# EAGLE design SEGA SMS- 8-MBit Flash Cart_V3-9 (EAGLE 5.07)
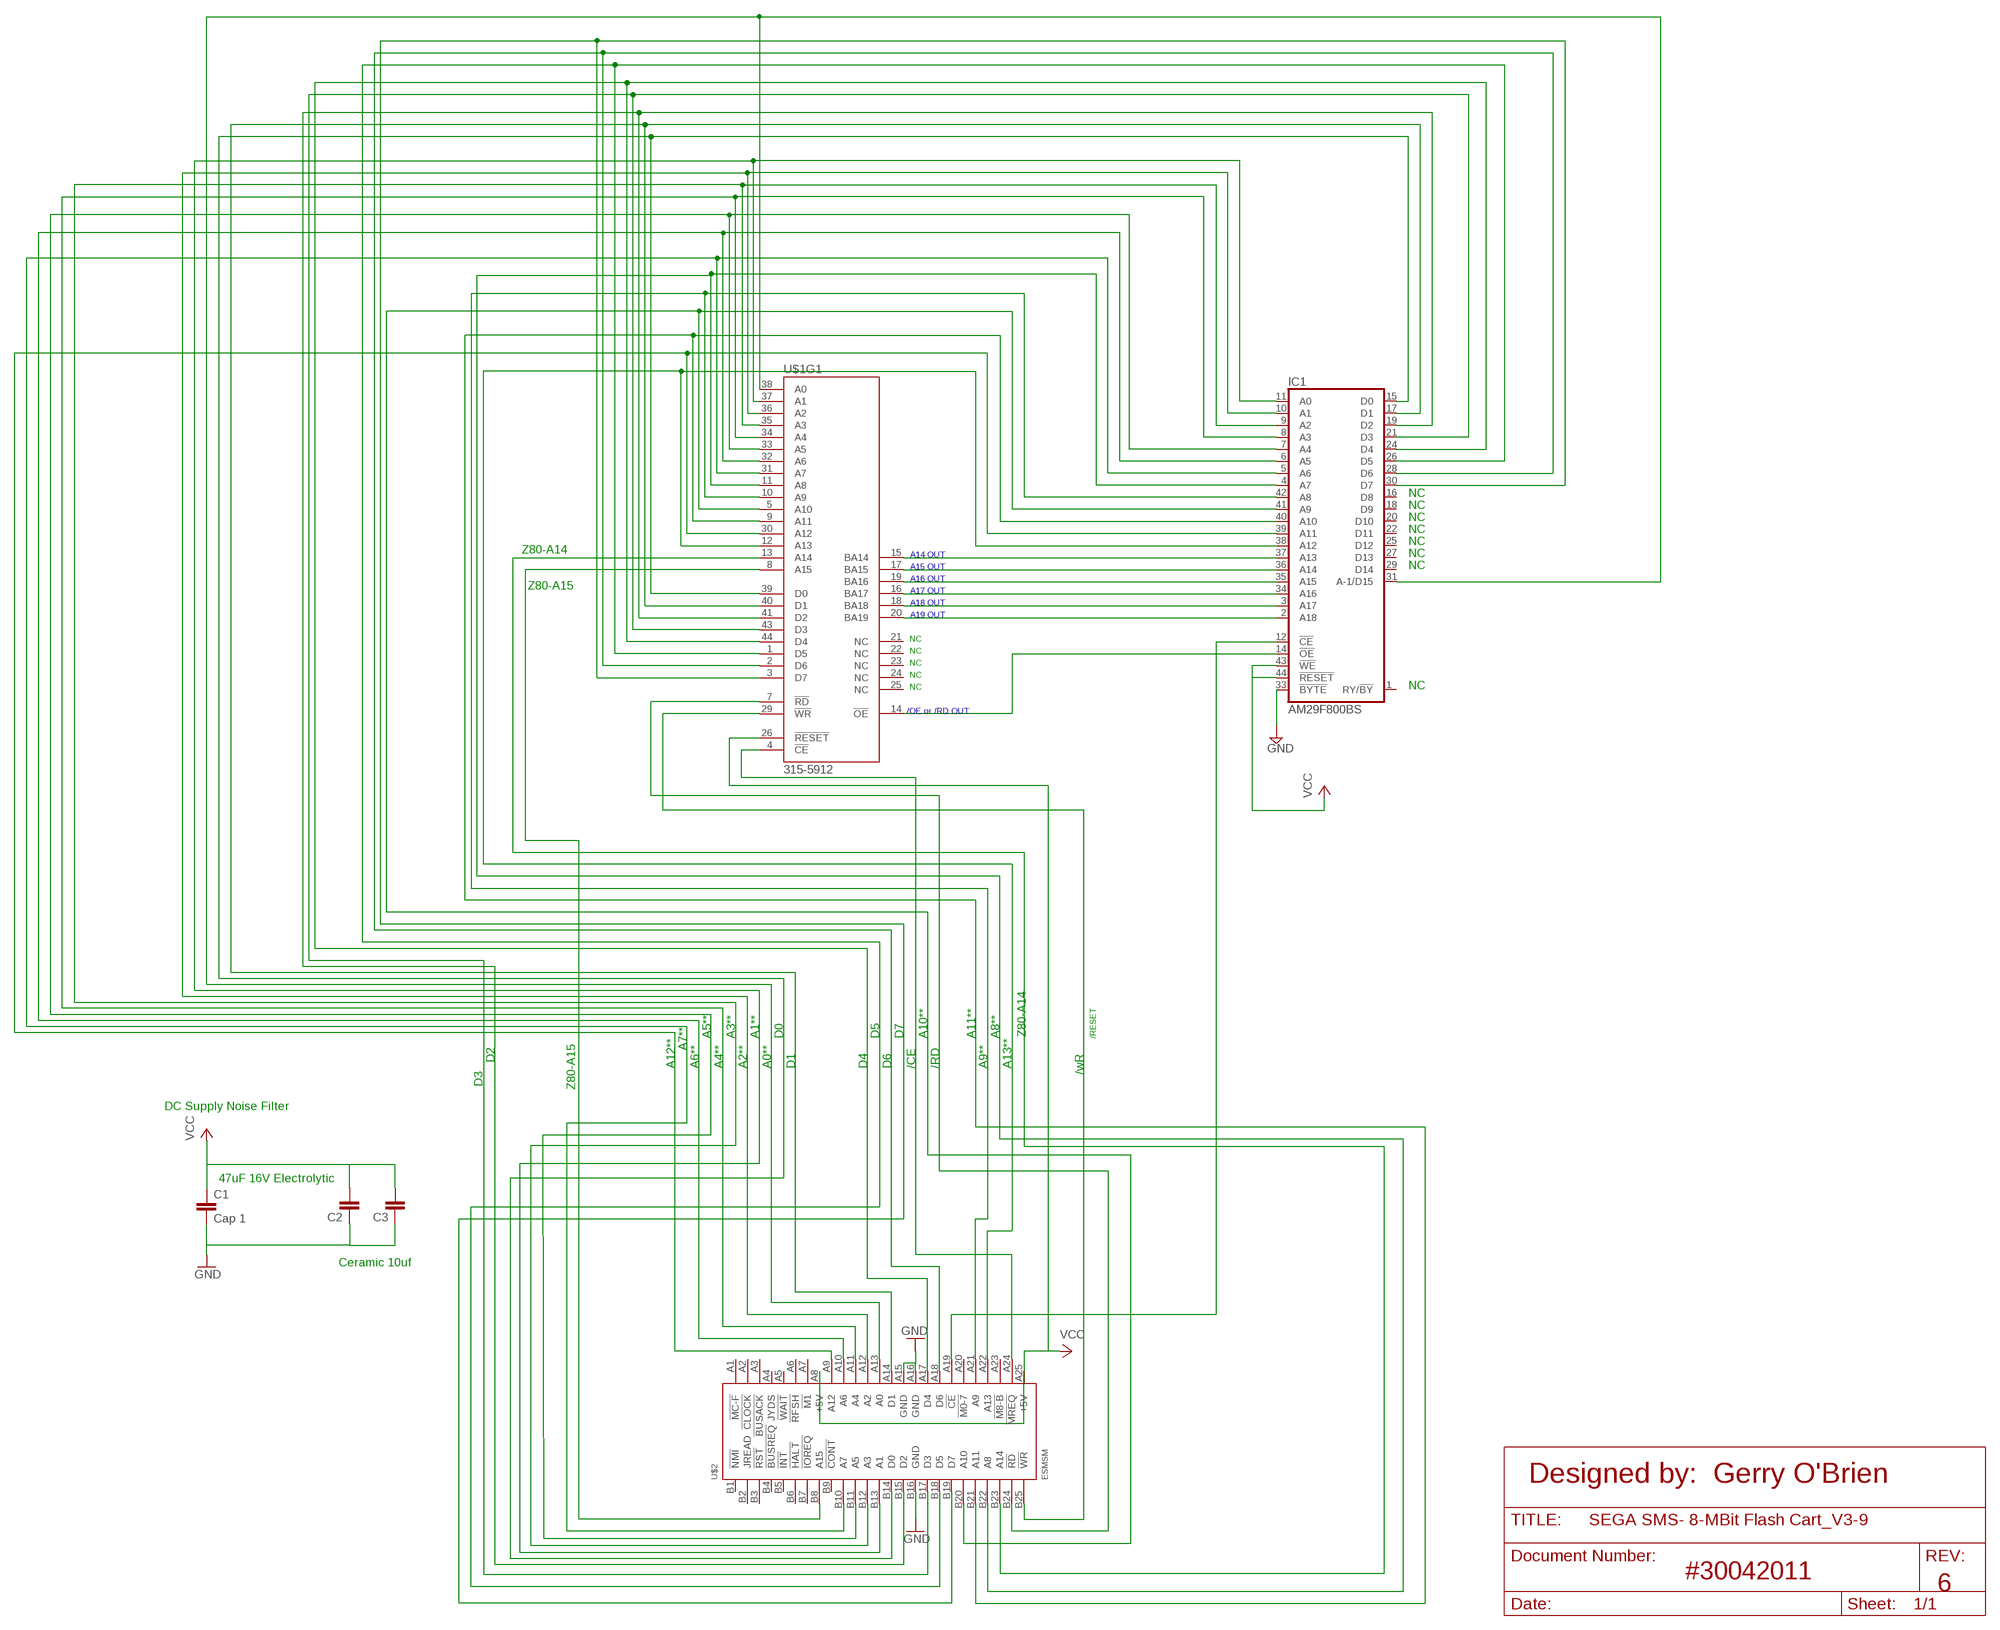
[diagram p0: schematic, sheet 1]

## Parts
C1  Cap 1  C7.5/3  [C7.5B3]
C2  CAP0805  [0805]
C3  CAP0805  [0805]
IC1  AM29F800BS  [SO44]
U$1  315-5912  [QFP-44]
U$2  ESMSM  [CARD50M]

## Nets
GND: C1.2 C2.1 C3.1 IC1.33(!BYTE) U$2.A15(GND) U$2.A16(GND) U$2.B16(GND)
N$1: IC1.39(A11) U$1.30(A12) U$2.A9(A12)
N$2: IC1.5(A6) U$1.31(A7) U$2.B10(A7)
N$3: IC1.41(A9) U$1.5(A10) U$2.B20(A10)
N$4: IC1.40(A10) U$1.9(A11) U$2.B21(A11)
N$5: IC1.31(A-1/D15) U$1.38(A0) U$2.A13(A0)
N$6: IC1.6(A5) U$1.32(A6) U$2.A10(A6)
N$7: IC1.38(A12) U$1.12(A13) U$2.A22(A13)
N$8: IC1.42(A8) U$1.10(A9) U$2.A21(A9)
N$9: IC1.24(D4) U$1.44(D4) U$2.A17(D4)
N$10: IC1.26(D5) U$1.1(D5) U$2.B18(D5)
N$11: IC1.14(!OE) U$1.14(!OE)
N$12: IC1.21(D3) U$1.43(D3) U$2.B17(D3)
N$13: IC1.12(!CE) U$2.A19(!CE)
N$14: IC1.17(D1) U$1.40(D1) U$2.A14(D1)
N$15: IC1.19(D2) U$1.41(D2) U$2.B15(D2)
N$16: IC1.15(D0) U$1.39(D0) U$2.B14(D0)
N$17: IC1.8(A3) U$1.34(A4) U$2.A11(A4)
N$18: IC1.11(A0) U$1.37(A1) U$2.B13(A1)
N$19: IC1.10(A1) U$1.36(A2) U$2.A12(A2)
N$20: IC1.34(A16) U$1.16(BA17)
N$21: IC1.7(A4) U$1.33(A5) U$2.B11(A5)
N$22: IC1.9(A2) U$1.35(A3) U$2.B12(A3)
N$24: IC1.37(A13) U$1.15(BA14)
N$25: IC1.4(A7) U$1.11(A8) U$2.B22(A8)
N$26: IC1.2(A18) U$1.20(BA19)
N$27: IC1.3(A17) U$1.18(BA18)
N$28: IC1.35(A15) U$1.19(BA16)
N$30: IC1.36(A14) U$1.17(BA15)
N$31: U$1.29(!WR) U$2.B25(!WR)
N$32: U$1.4(!CE) U$2.A24(!MREQ)
N$33: U$1.7(!RD) U$2.B24(!RD)
N$34: U$1.8(A15) U$2.B8(A15)
N$35: U$1.13(A14) U$2.B23(A14)
N$37: IC1.28(D6) U$1.2(D6) U$2.A18(D6)
N$38: IC1.30(D7) U$1.3(D7) U$2.B19(D7)
VCC: C1.1 C2.2 C3.2 IC1.43(!WE) IC1.44(!RESET) U$1.26(!RESET) U$2.A8(+5V) U$2.A25(+5V)
Unconnected: IC1.1(RY/!BY) IC1.16(D8) IC1.18(D9) IC1.20(D10) IC1.22(D11) IC1.25(D12) IC1.27(D13) IC1.29(D14) U$1.21(NC) U$1.22(NC) U$1.23(NC) U$1.24(NC) U$1.25(NC) U$2.A1(!MC-F) U$2.A2(!CLOCK) U$2.A3(!BUSACK) U$2.A4(JYDS) U$2.A5(!WAIT) U$2.A6(!RFSH) U$2.A7(!M1) U$2.A20(!M0-7) U$2.A23(!M8-B) U$2.B1(!NMI) U$2.B2(JREAD) U$2.B3(!RST) U$2.B4(!BUSREQ) U$2.B5(!INT) U$2.B6(!HALT) U$2.B7(!IOREQ) U$2.B9(!CONT)

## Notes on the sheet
- NC
- NC
- NC
- NC
- Z80-A14 | NC
- A14 OUT
- NC
- A15 OUT
- NC
- A16 OUT
- Z80-A15
- A17 OUT
- A18 OUT
- A19 OUT
- NC
- NC
- NC
- NC
- NC
- NC
- /OE or /RD OUT
- A5** | A3** | A1** | D0 | D5 | D7 | A10** | A11** | A8** | Z80-A14 | /RESET
- Z80-A15
- A7**
- D2
- A12** | A6** | A4** | A2** | A0** | D1 | D4 | D6 | /CE | /RD | A9** | A13**
- /wR
- D3
- DC Supply Noise Filter
- 47uF 16V Electrolytic
- Ceramic 10uf
- Designed by:  Gerry O'Brien
- #30042011
- 6

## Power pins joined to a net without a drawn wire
GND: U$1.6(GND) U$1.28(GND) U$1.42(GND)
VCC: IC1.23(VCC) U$1.27(VCC)
VSS: IC1.13(VSS) IC1.32(VSS)

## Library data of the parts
C1 = capacitor-wima:C: CAPACITOR
C2 C3 = SparkFun:CAP: Capacitor
IC1 = 2011.05.04:AM29F800B: 8 Megabit (1 M x 8-Bit/512 K x 16-Bit) CMOS 5.0 Volt-only Sector Erase Flash Memory PACKAGE TYPE E = 48-Pin Thin Small Outline Package (TSOP) Standard Pinout (TS 048) F = 48-Pin Thin Small Outline Package (TSOP) Reverse Pinout (TSR048) S = 44-Pin Small Outline Package (SO 044) DISTINCTIVE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
U$1 = 2010.09.20:315-5912: The 315-5912 Paging Chip The 315-5912 is known to support 8M. It is unknown whether this chip supports SRAM. Information from SMSPower.org Master System 8Mbit Eprom Cart for Sonic Blast, SEGA GameGear Flash Cart - Custom Electronics; as provided by jpx072, Gerry_MAN, Paul Baker, et. all Drawn by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
U$2 = 2010.09.20:ESMS: Sega Master System, outside Japan/Korea, cartridge port The ordering of the address and data pins allows for simple connection to common ROM and EPROM chips. description taken from SMSPower.org&micro; 2011.01.19 D Lue Choy

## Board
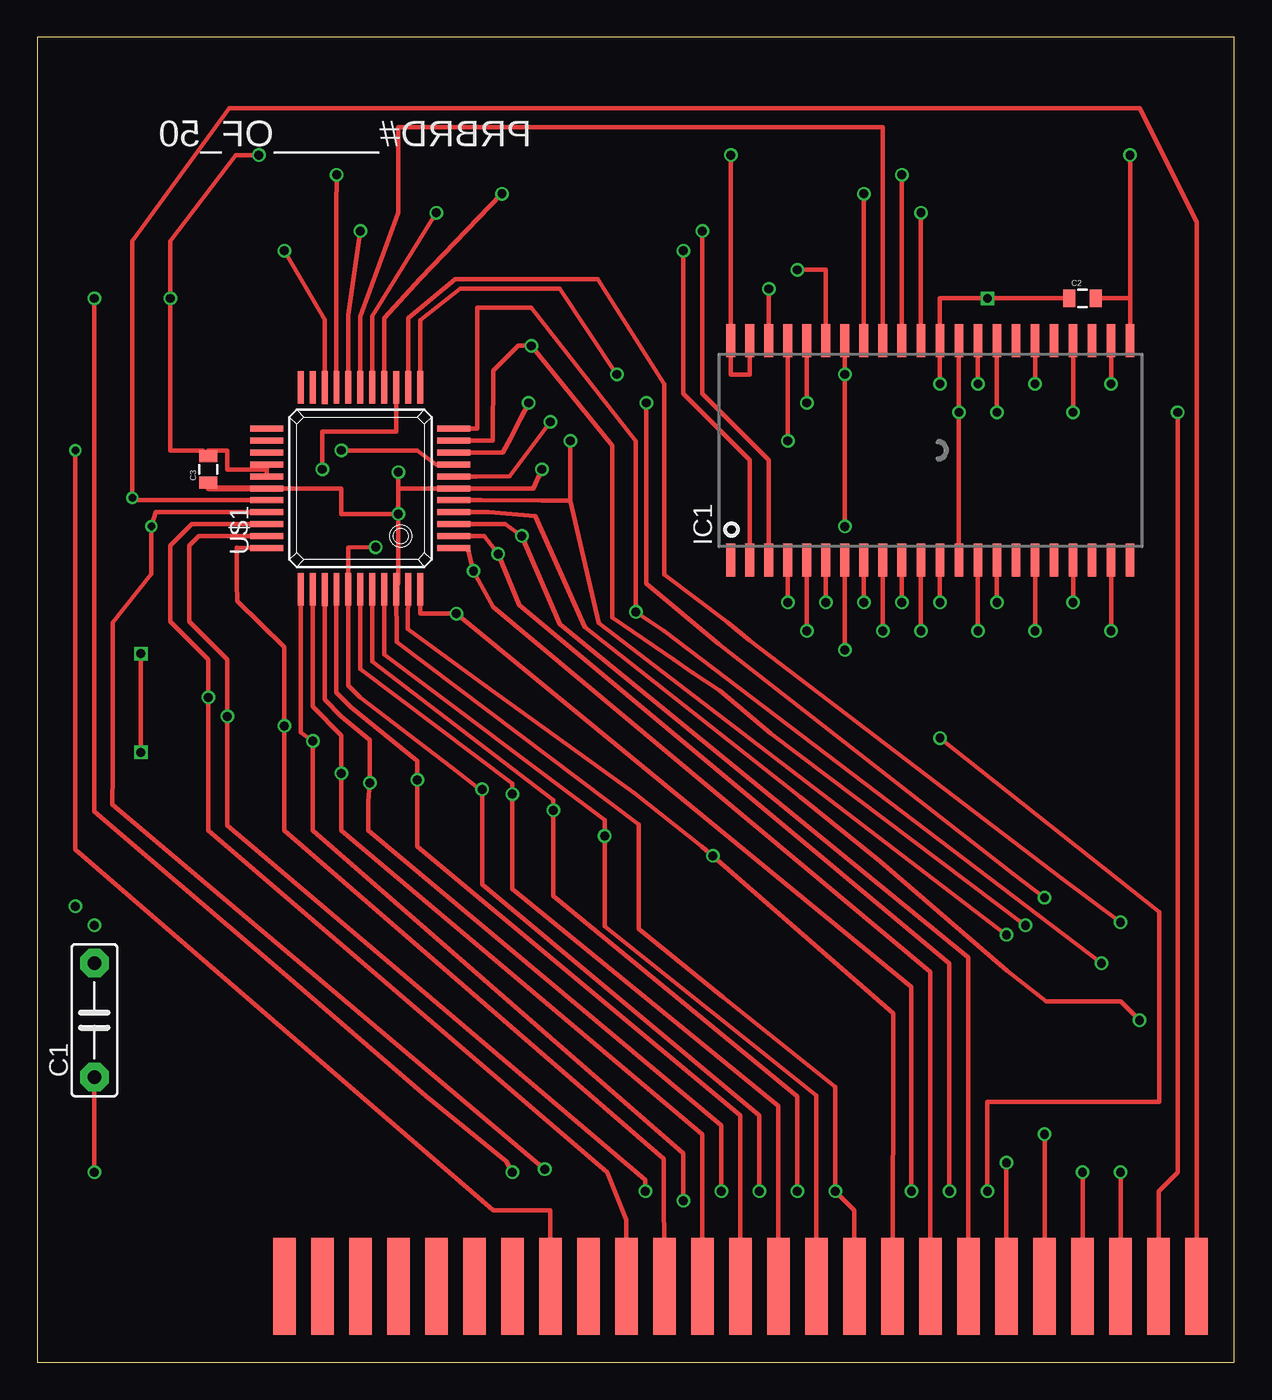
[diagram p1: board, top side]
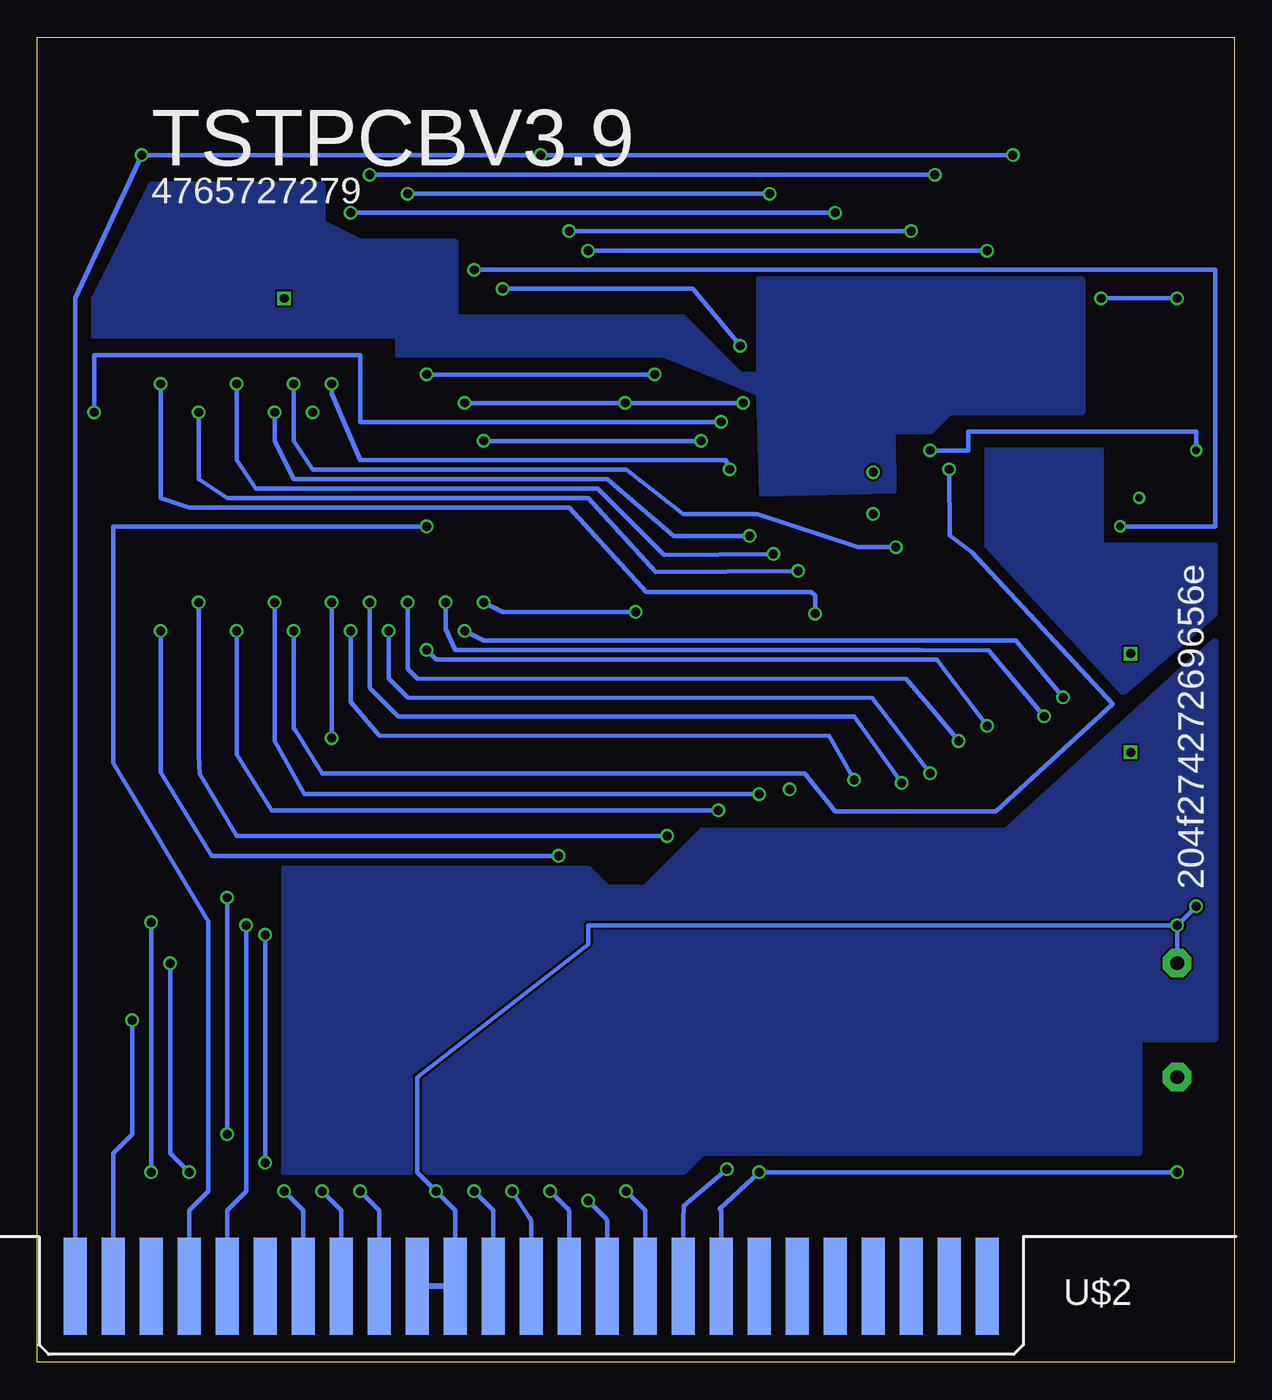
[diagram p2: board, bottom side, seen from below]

Size 79.99 x 88.57 mm. Coordinates in mm from the lower left corner, seen from the top.
Outline: 0,0 79.99,0 79.99,88.57 0,88.57 0,0
Copper layers (1*16): Top 0.035mm / dielectric 1.5mm / Bottom 0.035mm
Design rules "ITead_rule": minimum track width 6mil, minimum drill 12mil, track to track 6mil, track to pad 6mil, pad to pad 6mil, via to via 6mil, smd to smd 0mil, copper to edge 10mil, drill to drill 10mil, minimum pad ring 10mil, minimum via ring 6mil, stop-mask expansion 2mil, vias tented up to drill 100mil, thermal gap 10mil

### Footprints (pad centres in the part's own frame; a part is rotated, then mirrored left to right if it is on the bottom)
C7.5B3 = drill 0.914 pad 1.905 octagon: 1 -3.81,0; 2 3.81,0
0805 = smd 0.8 x 1.2: 1 -0.9,0; 2 0.9,0
SO44 = smd 0.6 x 2.2: 1 -13.335,-7.34; 2 -12.065,-7.34; 3 -10.795,-7.34; 4 -9.525,-7.34; 5 -8.255,-7.34; 6 -6.985,-7.34; 7 -5.715,-7.34; 8 -4.445,-7.34; 9 -3.175,-7.34; 10 -1.905,-7.34; 11 -0.635,-7.34; 12 0.635,-7.34; 13 1.905,-7.34; 14 3.175,-7.34; 15 4.445,-7.34; 16 5.715,-7.34; 17 6.985,-7.34; 18 8.255,-7.34; 19 9.525,-7.34; 20 10.795,-7.34; 21 12.065,-7.34; 22 13.335,-7.34; 23 13.335,7.34; 24 12.065,7.34; 25 10.795,7.34; 26 9.525,7.34; 27 8.255,7.34; 28 6.985,7.34; 29 5.715,7.34; 30 4.445,7.34; 31 3.175,7.34; 32 1.905,7.34; 33 0.635,7.34; 34 -0.635,7.34; 35 -1.905,7.34; 36 -3.175,7.34; 37 -4.445,7.34; 38 -5.715,7.34; 39 -6.985,7.34; 40 -8.255,7.34; 41 -9.525,7.34; 42 -10.795,7.34; 43 -12.065,7.34; 44 -13.335,7.34
QFP-44 = smd 0.4 x 2.2: 1 -4,-6.25; 2 -3.2,-6.25; 3 -2.4,-6.25; 4 -1.6,-6.25; 5 -0.8,-6.25; 6 0,-6.25; 7 0.8,-6.25; 8 1.6,-6.25; 9 2.4,-6.24; 10 3.2,-6.25; 11 4,-6.25; 23 4,6.25; 24 3.2,6.25; 25 2.4,6.26; 26 1.6,6.25; 27 0.8,6.25; 28 0,6.25; 29 -0.8,6.25; 30 -1.6,6.25; 31 -2.4,6.25; 32 -3.2,6.25; 33 -4,6.25 | smd 2.2 x 0.4: 12 6.75,-4; 13 6.75,-3.2; 14 6.75,-2.4; 15 6.75,-1.6; 16 6.75,-0.8; 17 6.75,0; 18 6.75,0.8; 19 6.75,1.6; 20 6.74,2.4; 21 6.75,3.2; 22 6.75,4; 34 -6.75,4; 35 -6.75,3.2; 36 -6.76,2.4; 37 -6.75,1.6; 38 -6.75,0.8; 39 -6.75,0; 40 -6.75,-0.8; 41 -6.75,-1.6; 42 -6.75,-2.4; 43 -6.75,-3.2; 44 -6.75,-4
CARD50M = smd 1.524 x 6.477: A1 -16.51,5.08; A2 -19.05,5.08; A3 -21.59,5.08; A4 -24.13,5.08; A5 -26.67,5.08; A6 -29.21,5.08; A7 -31.75,5.08; A8 -34.29,5.08; A9 -36.83,5.08; A10 -39.37,5.08; A11 -41.91,5.08; A12 -44.45,5.08; A13 -46.99,5.08; A14 -49.53,5.08; A15 -52.07,5.08; A16 -54.61,5.08; A17 -57.15,5.08; A18 -59.69,5.08; A19 -62.23,5.08; A20 -64.77,5.08; A21 -67.31,5.08; A22 -69.85,5.08; A23 -72.39,5.08; A24 -74.93,5.08; A25 -77.47,5.08 | smd 1.524 x 6.477 bottom: B1 -16.51,5.08; B2 -19.05,5.08; B3 -21.59,5.08; B4 -24.13,5.08; B5 -26.67,5.08; B6 -29.21,5.08; B7 -31.75,5.08; B8 -34.29,5.08; B9 -36.83,5.08; B10 -39.37,5.08; B11 -41.91,5.08; B12 -44.45,5.08; B13 -46.99,5.08; B14 -49.53,5.08; B15 -52.07,5.08; B16 -54.61,5.08; B17 -57.15,5.08; B18 -59.69,5.08; B19 -62.23,5.08; B20 -64.77,5.08; B21 -67.31,5.08; B22 -69.85,5.08; B23 -72.39,5.08; B24 -74.93,5.08; B25 -77.47,5.08

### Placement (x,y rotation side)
C1  3.81,22.86 90 top
C2  69.85,71.12 0 top
C3  11.43,59.69 90 top
IC1  59.69,60.96 0 top
U$1  21.59,58.42 90 top
U$2  0,0 0 bottom

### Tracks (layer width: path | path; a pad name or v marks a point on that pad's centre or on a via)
GND  (via drill 0.6)
  Top 0.254: U$1.42 24.13,52.07 | 26.67,58.42 U$1.6
  Top 0.305: v24.13,56.71 20.32,56.71 20.32,58.42 U$1.28 | v24.13,56.71 24.13,58.42 26.67,58.42 | 24.13,52.07 v24.13,56.71 | v60.33,65.41 IC1.33 60.33,71.12 v63.5,71.12 C2.1 | U$1.6 33.15,58.42 v33.72,59.69 | U$1.42 24,48.13 40.2,35.94 40.2,28.96 45.85,24.38 53.34,18.41 v53.34,11.43 54.61,10.16 U$2.B16 54.61,3.81 | 11.43,58.42 C3.1 | v24.13,56.71 v24.13,59.5
  Top 0.406: U$1.28 11.43,58.42
  Bottom 0.305: v60.33,65.41 60.33,64.77 58.42,60.33 33.97,60.33 v33.72,59.69 | U$2.A15 52.07,10.16 v53.34,11.43 54.61,12.7 54.61,19.05 43.18,27.94 43.18,29.21 v3.81,29.21 | C1.2 v3.81,29.21 | v3.81,29.21 v2.54,30.48
  Bottom 0.406: U$2.A15 U$2.B16
N$1  (via drill 0.5, 0.6)
  Top 0.305: U$1.30 7.92,56.82 v7.62,55.88 7.62,52.7 5.05,49.44 5.05,39.34 5.02,37.27 v33.91,12.89 | IC1.39 52.7,73.03 v50.8,73.03
  Bottom 0.305: v33.91,12.89 36.8,10.44 36.83,9.49 U$2.A9 | v50.8,73.03 1.27,73.03 1.27,55.88 v7.62,55.88
N$2  (via drill 0.6)
  Top 0.305: U$1.31 10.3,56.02 8.89,54.61 8.89,49.53 11.43,46.99 v11.43,44.45 11.43,35.56 38.1,12.7 39.37,9.53 U$2.B10 | v51.44,48.9 IC1.5
  Bottom 0.305: v51.44,48.9 50.16,48.26 14.61,48.26 v11.43,44.45
N$3  (via drill 0.6)
  Top 0.305: U$1.5 29.68,57.62 33.72,57.59 35.62,57.59 | 35.62,57.59 37.53,49.4 v64.77,28.57 | v50.16,61.59 IC1.41 | 35.62,57.59 v35.62,61.59 | U$2.B20 v64.77,13.34
  Bottom 0.305: v35.62,61.59 v50.16,61.59 | v64.77,13.34 v64.77,28.57
N$4  (via drill 0.6)
  Top 0.305: U$1.9 31.11,60.82 31.62,61.78 32.26,63.06 v32.83,64.14 | v51.44,64.14 IC1.40 | U$2.B21 v67.31,15.24 | v67.31,31.05 65.22,32.64 45.53,48.01 40.7,52.07 v40.7,64.14
  Bottom 0.305: v32.83,64.14 v40.7,64.14 v51.44,64.14 | v67.31,15.24 v67.31,31.05
N$5  (via drill 0.6)
  Top 0.305: v62.87,65.41 IC1.31 | v22.61,54.48 20.79,54.45 U$1.38 20.79,45.25 21.59,44.45 27.69,39.75 29.65,38.23 v29.72,38.29 29.72,31.94 48.26,16.51 v48.26,11.43
  Bottom 0.305: v62.87,65.41 62.87,61.59 61.59,59.69 40.64,59.69 36.83,56.71 31.88,56.71 25.15,54.48 v22.61,54.48 | U$2.A13 46.99,9.39 arc-45 47.08,9.62 v48.26,11.43
N$6  (via drill 0.6)
  Top 0.305: U$1.32 10.77,55.22 10.16,54.61 10.16,49.53 12.7,46.99 v12.7,43.18 12.7,35.88 13.97,34.8 40.64,12.19 v40.64,11.43 | v52.7,50.8 IC1.6
  Bottom 0.305: U$2.A10 39.37,10.16 v40.64,11.43 | v52.7,50.8 52.7,49.03 52.07,47.62 20.95,47.62 16.41,47.59 v12.7,43.18
N$7  (via drill 0.6)
  Top 0.305: U$1.12 25.59,69.66 28.26,71.75 34.92,71.75 v38.73,66.04 | IC1.38 v53.98,66.04 v53.98,55.88
  Bottom 0.305: U$2.A22 69.85,10.16 68.58,11.43 68.58,29.46 74.93,40.07 74.93,55.88 v53.98,55.88 | v53.98,66.04 v38.73,66.04
N$8  (via drill 0.6)
  Top 0.305: U$1.10 30.44,61.62 30.48,66.29 32.13,67.94 v33.02,67.94 38.42,61.28 38.42,49.78 42.55,46.99 43.75,46.1 45.59,44.9 49.02,42.04 v66.04,29.21 | v48.9,71.75 IC1.42
  Bottom 0.305: v33.02,67.94 36.2,71.75 v48.9,71.75 | U$2.A21 67.31,10.16 66.04,11.43 v66.04,29.21
N$9  (via drill 0.6)
  Top 0.305: U$1.44 25.59,50.61 25.59,50.04 v28,50.04 58.42,25.08 v58.42,11.43 | v71.75,65.41 IC1.24
  Bottom 0.305: v71.75,65.41 71.75,57.78 69.85,57.15 44.45,57.15 39.31,51.5 28.26,51.5 28,51.24 v28,50.04 | v58.42,11.43 57.15,10.16 U$2.A17
N$10  (via drill 0.6)
  Top 0.305: U$1.1 28.77,54.42 v29.15,52.9 30.48,50.48 59.69,26.1 U$2.B18 | v69.22,63.5 IC1.26
  Bottom 0.305: v69.22,63.5 69.22,59.05 67.31,57.78 43.18,57.78 38.67,52.83 v29.15,52.9
N$11  (via drill 0.6)
  Top 0.305: v62.87,48.9 IC1.14 | U$1.14 23.99,62.22 19.07,62.22 arc-45 19.05,62.23 v19.05,59.69
  Bottom 0.305: v62.87,48.9 62.87,42.49 arc-45 62.77,42.26 60.96,39.37 28.71,39.37 26.67,36.83 15.94,36.83 8.13,44.01 17.53,54.17 19.02,55.28 v19.05,59.69
N$12  (via drill 0.6)
  Top 0.305: U$1.43 24.79,51.28 24.77,49.59 24.77,49.02 29.97,45.21 39.88,38.04 44.39,34.48 v45.15,33.85 57.21,23.3 57.21,16.76 U$2.B17 | v71.75,48.9 IC1.21
  Bottom 0.305: v71.75,48.9 71.75,39.43 68.33,33.85 v45.15,33.85
N$13  (via drill 0.6)
  Top 0.305: v60.33,50.8 IC1.12 | v63.5,11.43 63.5,17.4 74.99,17.4 74.99,30.1 v60.33,41.72
  Bottom 0.305: U$2.A19 62.23,10.16 v63.5,11.43 | v60.33,41.72 v60.33,50.8
N$14  (via drill 0.6)
  Top 0.305: U$1.40 22.39,46.83 34.48,37.59 v34.48,36.89 34.48,31.18 50.8,17.78 v50.8,11.43 | v66.67,48.9 IC1.17
  Bottom 0.305: v66.67,48.9 66.67,40.64 64.33,36.89 v34.48,36.89 | U$2.A14 49.53,10.16 v50.8,11.43
N$15  (via drill 0.6)
  Top 0.305: U$1.41 23.19,47.3 37.91,36.26 v37.91,35.18 37.91,29.15 52.07,17.84 U$2.B15 | v69.22,50.8 IC1.19
  Bottom 0.305: v69.22,50.8 69.22,40.51 69.15,39.31 66.67,35.18 v37.91,35.18
N$16  (via drill 0.6)
  Top 0.305: U$1.39 21.59,46.35 31.75,38.67 v31.75,37.97 31.75,31.62 49.53,17.14 U$2.B14 | v64.14,50.8 IC1.15
  Bottom 0.305: v64.14,50.8 64.14,41.53 62.17,37.97 v31.75,37.97
N$17  (via drill 0.6)
  Top 0.305: U$1.34 17.59,42.1 v18.41,41.53 18.41,35.56 43.18,13.97 v43.18,10.79 | v55.24,50.8 IC1.8
  Bottom 0.305: v55.24,50.8 55.24,46.35 54.61,45.72 21.91,45.66 20.32,43.81 v18.41,41.53 | U$2.A11 41.91,9.39 arc-45 42,9.62 v43.18,10.79
N$18  (via drill 0.6)
  Top 0.305: U$1.37 19.99,44.78 20.95,43.81 25.4,40.2 v25.4,38.92 25.4,34.48 46.99,16.51 U$2.B13 | v59.05,48.9 IC1.11
  Bottom 0.305: v59.05,48.9 59.05,44.13 57.15,41.91 27.05,41.85 v25.4,38.92
N$19  (via drill 0.6)
  Top 0.305: U$1.36 19.19,44.31 20.32,43.18 22.23,41.59 v22.23,38.73 22.1,37.47 22.1,35.56 45.69,15.84 45.72,13.97 v45.72,11.43 | v57.78,50.8 IC1.10
  Bottom 0.305: v57.78,50.8 57.78,45.09 55.88,43.18 25.4,43.18 v22.23,38.73 | U$2.A12 44.45,10.03 arc-45 44.54,10.25 v45.72,11.43
N$20  (via drill 0.6)
  Top 0.305: U$1.16 22.39,69.94 v26.67,76.83 | v59.05,76.83 IC1.34
  Bottom 0.305: v26.67,76.83 v59.05,76.83
N$21  (via drill 0.6)
  Top 0.305: U$2.B11 41.85,13.59 16.51,35.56 v16.51,42.55 16.51,47.82 13.34,50.87 13.34,52.08 13.34,54.46 U$1.33 | v53.98,47.62 IC1.7
  Bottom 0.305: v53.98,47.62 53.34,46.99 19.88,46.99 v16.51,42.55
N$22  (via drill 0.6)
  Top 0.305: U$1.35 18.39,43.84 20.32,41.91 v20.32,39.37 20.32,35.56 44.45,15.24 U$2.B12 | v56.52,48.9 IC1.9
  Bottom 0.305: v56.52,48.9 56.52,45.72 55.24,44.45 24.19,44.39 v20.32,39.37
N$24  (via drill 0.6)
  Top 0.305: U$1.15 23.19,69.8 25.59,72.45 v31.05,78.11 | v55.24,78.11 IC1.37
  Bottom 0.305: v31.05,78.11 v55.24,78.11
N$25  (via drill 0.6)
  Top 0.305: U$1.11 29.4,62.42 29.4,70.48 33.02,70.48 40.01,61.59 v40.01,50.16 41.91,48.9 v71.12,26.67 | v50.16,50.8 IC1.4 | U$2.B22 v69.85,12.7
  Bottom 0.305: v69.85,12.7 71.12,13.97 v71.12,26.67 | v40.01,50.16 48.9,50.16 v50.16,50.8
N$26  (via drill 0.6)
  Top 0.305: U$1.20 19.19,69.71 v16.51,74.3 | IC1.2 47.62,60.33 43.18,64.77 v43.18,74.3
  Bottom 0.305: v16.51,74.3 v43.18,74.3
N$27  (via drill 0.6)
  Top 0.305: U$1.18 20.79,70.02 v21.59,75.63 | IC1.3 48.9,60.33 44.45,64.77 v44.45,75.63
  Bottom 0.305: v21.59,75.63 v44.45,75.63
N$28  (via drill 0.6)
  Top 0.305: v57.78,79.38 IC1.35 | U$1.19 19.99,77.08 v20,79.38
  Bottom 0.305: v20,79.38 v57.78,79.38
N$29
  pour Bottom: 36.83,12.7 63.5,12.7 63.5,33.02 43.18,33.02 41.91,31.75 39.37,31.75 35.56,35.56 15.24,35.56 4.25,45.59 1.27,48.26 1.27,21.59 6.35,21.59 6.35,13.97 35.56,13.97
N$30
  Top 0.305: U$1.17 21.59,69.91 24.13,76.83 24.13,82.55 56.52,82.55 IC1.36
N$31  (via drill 0.5)
  Top 0.305: U$1.29 6.35,57.62 v6.35,57.78 6.35,74.93 12.83,83.82 73.66,83.82 77.47,76.2 U$2.B25
N$32  (via drill 0.6)
  Top 0.305: U$1.4 30.15,56.82 33.27,56.58 36.58,49.15 50.99,37.78 56.33,33.47 64.83,26.16 67.44,24.13 72.39,24.13 v73.66,22.86
  Bottom 0.305: U$2.A24 74.93,13.97 73.66,15.24 v73.66,22.86
N$33  (via drill 0.6)
  Top 0.305: U$2.B24 74.93,11.43 76.2,12.7 v76.2,63.5 | U$1.7 29.38,59.22 31.56,59.24 v34.29,62.87
  Bottom 0.305: v34.29,62.87 58.42,62.87 58.42,67.31 76.2,67.31 v76.2,63.5
N$34  (via drill 0.5, 0.6)
  Top 0.305: U$2.B8 34.29,10.16 30.48,10.16 2.54,34.29 v2.54,60.96 | U$1.8 26.67,60.02 25.4,60.96 v20.32,60.96
  Bottom 0.305: v2.54,60.96 2.54,62.23 17.78,62.23 17.78,60.96 v20.32,60.96
N$35  (via drill 0.6)
  Top 0.305: U$1.13 24.79,69.81 27.94,72.39 37.47,72.39 41.91,65.41 41.91,52.64 46.1,49.47 47.62,48.26 68.45,32.32 v72.39,29.4 | U$2.B23 v72.39,12.7
  Bottom 0.305: v72.39,12.7 v72.39,29.4
N$36
  pour Bottom: 1.27,54.61 8.89,54.61 8.89,60.96 16.51,60.96 16.51,54.61 7.43,44.77 1.27,50.04
N$37  (via drill 0.6)
  Top 0.305: U$1.2 29.87,55.22 v30.8,54.04 32.19,50.61 60.96,26.67 v60.96,11.43 | v66.67,65.41 IC1.28
  Bottom 0.305: v66.67,65.41 66.67,60.33 65.41,58.42 42.55,58.42 38.1,53.98 v30.8,54.04 | U$2.A18 59.69,10.16 v60.96,11.43
N$38  (via drill 0.6)
  Top 0.305: U$1.3 31.25,56.02 v32.38,55.24 34.92,49.34 62.23,27.05 U$2.B19 | v64.14,63.5 IC1.30
  Bottom 0.305: v64.14,63.5 64.14,61.59 62.87,59.05 41.91,59.05 37.47,55.24 v32.38,55.24
N$39
  pour Bottom: 10.16,72.39 10.16,63.5 19.05,63.5 20.32,62.23 22.86,62.23 22.8,59.31 22.8,58.23 31.56,58.04 31.75,64.77 38.1,67.31 55.88,67.31 55.88,68.58 76.2,68.58 76.2,71.12 72.39,78.74 60.96,78.74 60.96,76.2 58.42,74.93 52.07,74.93 52.07,69.85 36.83,69.85 33.02,66.04 31.75,66.04 31.75,72.39
N$41  (via drill 0.6)
  Top 0.305: v6.92,40.77 v6.92,47.37
VCC  (via drill 0.6)
  Top 0.305: v73.03,80.71 73.03,71.12 | 73.03,71.12 IC1.23 | IC1.43 47.62,66.04 46.35,66.04 IC1.44 v46.35,80.71 | v31.75,12.7 31.34,13.43 25.97,17.81 16.44,26.04 3.81,36.83 v3.81,71.12 | U$1.27 U$1.26 15.24,59.69 12.7,59.69 12.7,60.96 11.43,60.96 C3.2 11.06,60.96 8.89,60.96 v8.89,71.12 8.89,74.93 13.27,80.71 v14.8,80.71 | 73.03,71.12 C2.2 | v3.81,12.7 C1.1
  Bottom 0.305: U$2.A25 77.47,71.12 v73.03,80.71 v46.35,80.71 v14.8,80.71 | U$2.A8 34.29,10.03 arc-45 34.38,10.25 v31.75,12.7 v3.81,12.7 | v3.81,71.12 v8.89,71.12
VSS  (via drill 0.6)
  Top 0.305: IC1.32 v61.59,63.5 IC1.13

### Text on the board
tNames: PRBRD#_____OF_50
bNames: TSTPCBV3.9 | 4765727279 | 204f27427269656e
